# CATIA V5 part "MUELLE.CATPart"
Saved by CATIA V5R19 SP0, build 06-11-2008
Material "Titanium": density 4460 kg/m3, Young's modulus 1.14e+11 Pa, Poisson ratio 0.34, thermal expansion 9.5e-06 1/K
Bounding box of the stored display mesh (mm): x -2.25 to 2.25, y -2.25 to 2.25, z -1.75 to 21.749
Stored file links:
  D:\TR\libro\ejemplo\terminados\BOLIGRAFO\MUELLE.CATPart
  D:\TR\libro\ejemplo\terminados\BOLIGRAFO\Grupo boligrafo.CATProduct
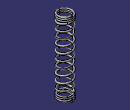
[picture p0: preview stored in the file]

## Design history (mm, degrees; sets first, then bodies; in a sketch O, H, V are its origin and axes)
AxisSystem1: origin (0, 0, 0), X (1, 0, 0), Y (0, 1, 0), Z (0, 0, 1)
Body1 (main body)
  Sketch1 on YZ plane of AxisSystem1, origin (0, 0, 0), H (0, 1, 0), V (0, 0, 1)
    point P1 (2, 0)
    distance P1 V = 2
    coincidence: P1 H
  Helix1: Pitch 2, TaperAngle 0, Height 20, Direction Sketch1.V, RefPoint Sketch1
  Helix2: Pitch 0.5, TaperAngle 0, Height 1.5, Direction Sketch1.V, RefPoint Sketch1
  Helix3: Pitch 0.5, TaperAngle 0, Height 1.5, Direction edge [ZX plane of AxisSystem1 | YZ plane of AxisSystem1], RefPoint vertex of Helix1
  Point1: type OnCurve, Support Helix1, Length 1
  Point2: type OnCurve, Support Helix2, Length 1
  Connect1: Curve1 Helix1, Curve2 Helix2, Tension1 1, Tension2 1, Point1 Point1, Point2 Point2
  Split1: ToCut Helix1, Cutting Connect1
  Split2: ToCut Helix2, Cutting Connect1
  Point3: type OnCurve, Support Helix3, Length 1
  Point4: type OnCurve, Support Split1, Length 1
  Connect2: Curve1 Helix3, Curve2 Split1, Tension1 1, Tension2 1, Point1 Point3, Point2 Point4
  Split3: ToCut Helix3, Cutting Connect2
  Split4: ToCut Split1, Cutting Connect2
  Join1: Elements (Split3; Connect2; Split4; Connect1; Split2)
  Sketch2 on YZ plane of AxisSystem1, origin (0, 0, 0), H (0, 1, 0), V (0, 0, 1)
    circle A1 centre (2, -1.5) radius 0.25
    radius A1 = 0.25
  Rib1: profile Sketch2, centre curve Join1
Body2
  Set1 "Referencias"
    Sketch3 on YZ plane of AxisSystem1, origin (0, 0, 0), H (0, 1, 0), V (0, 0, 1)
      point P1 (2, 0)
      distance P1 V = 2
      coincidence: P1 H
    Helix4: Pitch 2, TaperAngle 0, Height 20, Direction Sketch3.V, RefPoint Sketch3
    Helix5: Pitch 0.5, TaperAngle 0, Height 1.5, Direction Sketch3.V, RefPoint Sketch3
    Helix6: Pitch 0.5, TaperAngle 0, Height 1.5, Direction edge [ZX plane of AxisSystem1 | YZ plane of AxisSystem1], RefPoint vertex of Helix4
    Point5: type OnCurve, Support Helix4, Length 1
    Point6: type OnCurve, Support Helix5, Length 1
    Connect3: Curve1 Helix4, Curve2 Helix5, Tension1 1, Tension2 1, Point1 Point5, Point2 Point6
    Split5: ToCut Helix4, Cutting Connect3
    Split6: ToCut Helix5, Cutting Connect3
    Point7: type OnCurve, Support Helix6, Length 1
    Point8: type OnCurve, Support Split5, Length 1
    Connect4: Curve1 Helix6, Curve2 Split5, Tension1 1, Tension2 1, Point1 Point7, Point2 Point8
    Split7: ToCut Helix6, Cutting Connect4
    Split8: ToCut Split5, Cutting Connect4
    Join2: Elements (Split7; Connect4; Split8; Connect3; Split6)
